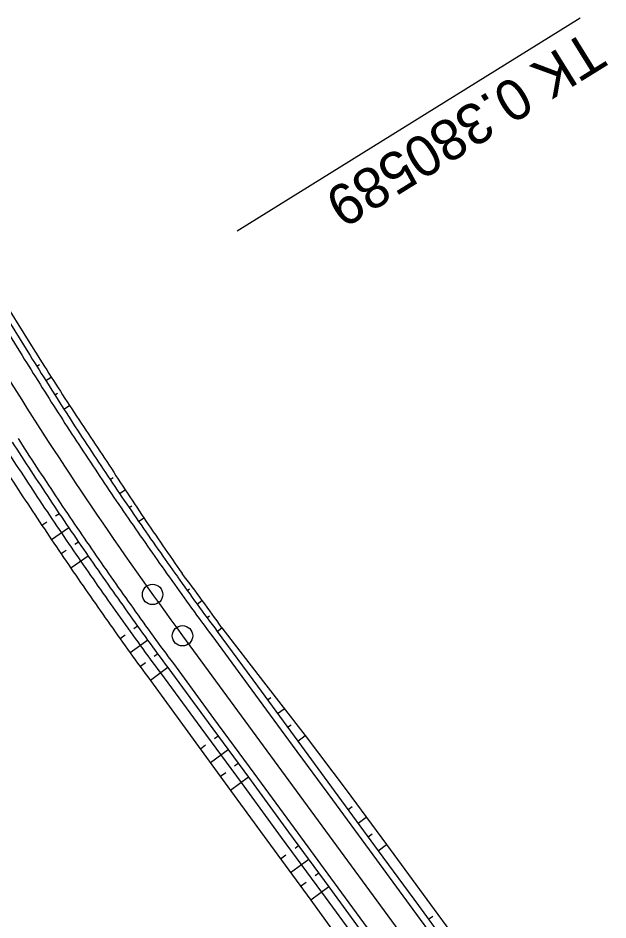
# Model space of a CAD drawing. Extents: x -481645 to -478728, y -1113199 to -1110710.
# Drawn here: x -480676.8 to -480633.4, y -1112872.3 to -1112806 of the extents above; entities that cross this region are included whole.
import ezdxf

# ---------------------------------------------------------------- set-up
doc = ezdxf.new("R2010")
doc.units = 0
for name, color, linetype in [('CP14_HATCH_SLOPE_R', 7, 'Continuous'), ('Vrstva 31', 7, 'Continuous'), ('Vrstva 32', 7, 'Continuous'), ('Vrstva 33', 7, 'Continuous'), ('Vrstva 34', 7, 'Continuous'), ('Vrstva 35', 7, 'Continuous'), ('Vrstva 37', 7, 'Continuous'), ('Vrstva 38', 7, 'Continuous'), ('Vrstva 39', 7, 'Continuous'), ('Vrstva 40', 7, 'Continuous')]:
    doc.layers.add(name, color=color, linetype=linetype)

msp = doc.modelspace()

# ---------------------------------------------------------------- linework, layer by layer
at = {"layer": 'CP14_HATCH_SLOPE_R'}
msp.add_line((-480664.724, -1112851.371), (-480634.276, -1112892.852), dxfattribs=at)
msp.add_arc((-480422.88, -1112673.855), 300, 211.85533, 216.27914, dxfattribs=at)
at = {"layer": 'Vrstva 31'}
for p, q in [((-480678.345, -1112826.011), (-480675.701, -1112830.255)), ((-480661.821, -1112850.789), (-480658.769, -1112854.751)), ((-480667.082, -1112854.65), (-480664.139, -1112858.692)), ((-480658.769, -1112854.751), (-480655.715, -1112858.711)), ((-480664.139, -1112858.692), (-480661.194, -1112862.733)), ((-480655.715, -1112858.711), (-480652.699, -1112862.7)), ((-480661.194, -1112862.733), (-480658.249, -1112866.774)), ((-480652.699, -1112862.7), (-480649.732, -1112866.725)), ((-480658.249, -1112866.774), (-480655.301, -1112870.813)), ((-480649.732, -1112866.725), (-480646.765, -1112870.749)), ((-480655.301, -1112870.813), (-480652.355, -1112874.852)), ((-480646.765, -1112870.749), (-480643.798, -1112874.774))]:
    msp.add_line(p, q, dxfattribs=at)
for centre, radius, start, end in [((-479922.472, -1112352.852), 891.778, 212.366886, 212.685556), ((-480424.277, -1112671.739), 297.238, 213.18635, 214.14131), ((-480423.024, -1112673.635), 303.787, 212.74733, 213.70226), ((-480420.584, -1112677.294), 297.252, 212.85556, 213.81059), ((-480422.254, -1112674.783), 303.794, 213.44157, 214.39651), ((-480421.236, -1112676.22), 297.31, 214.05258, 215.00756), ((-480422.209, -1112674.815), 303.813, 214.38669, 215.34163), ((-480783.207, -1112936.622), 148.667, 35.26462, 37.17881), ((-480545.358, -1112763.764), 151.912, 214.84324, 216.74722)]:
    msp.add_arc(centre, radius, start, end, dxfattribs=at)
at = {"layer": 'Vrstva 32'}
for p, q in [((-480666.336, -1112854.103), (-480663.378, -1112858.133)), ((-480663.378, -1112858.133), (-480660.419, -1112862.164)), ((-480660.419, -1112862.164), (-480657.46, -1112866.195)), ((-480657.46, -1112866.195), (-480654.502, -1112870.226)), ((-480654.502, -1112870.226), (-480651.543, -1112874.256))]:
    msp.add_line(p, q, dxfattribs=at)
for centre, radius, start, end in [((-480422.881, -1112673.855), 302.916, 212.69777, 213.6527), ((-480422.881, -1112673.855), 302.916, 213.6527, 214.60763), ((-480422.881, -1112673.855), 302.916, 214.60763, 215.56256), ((-480545.316, -1112763.033), 151.458, 215.05694, 216.96228)]:
    msp.add_arc(centre, radius, start, end, dxfattribs=at)
at = {"layer": 'Vrstva 33'}
for p, q in [((-480678.734, -1112826.253), (-480676.095, -1112830.5)), ((-480662.171, -1112851.046), (-480659.213, -1112855.076)), ((-480665.799, -1112853.708), (-480662.84, -1112857.739)), ((-480659.213, -1112855.076), (-480656.254, -1112859.107)), ((-480662.84, -1112857.739), (-480659.882, -1112861.77)), ((-480656.254, -1112859.107), (-480653.296, -1112863.138)), ((-480659.882, -1112861.77), (-480656.923, -1112865.801)), ((-480653.296, -1112863.138), (-480650.337, -1112867.169)), ((-480656.923, -1112865.801), (-480653.965, -1112869.831)), ((-480650.337, -1112867.169), (-480647.378, -1112871.199)), ((-480653.965, -1112869.831), (-480651.006, -1112873.862)), ((-480647.378, -1112871.199), (-480644.42, -1112875.23))]:
    msp.add_line(p, q, dxfattribs=at)
for centre, radius, start, end in [((-479919.133, -1112356.26), 893.25, 212.067306, 212.385897), ((-480422.881, -1112673.855), 297.75, 212.69777, 213.6527), ((-480422.881, -1112673.855), 302.25, 212.69777, 213.6527), ((-480422.881, -1112673.855), 297.75, 213.6527, 214.60763), ((-480422.881, -1112673.855), 302.25, 213.6527, 214.60763), ((-480422.881, -1112673.855), 297.75, 214.60763, 215.56256), ((-480422.881, -1112673.855), 302.25, 214.60763, 215.56256), ((-480543.224, -1112761.518), 148.875, 215.05399, 216.96753), ((-480545.046, -1112762.837), 151.125, 215.05656, 216.96295)]:
    msp.add_arc(centre, radius, start, end, dxfattribs=at)
at = {"layer": 'Vrstva 34'}
for p, q in [((-480679.159, -1112826.517), (-480676.52, -1112830.764)), ((-480662.574, -1112851.342), (-480659.616, -1112855.372)), ((-480665.396, -1112853.413), (-480662.437, -1112857.443)), ((-480659.616, -1112855.372), (-480656.657, -1112859.403)), ((-480662.437, -1112857.443), (-480659.479, -1112861.474)), ((-480656.657, -1112859.403), (-480653.699, -1112863.434)), ((-480659.479, -1112861.474), (-480656.52, -1112865.505)), ((-480653.699, -1112863.434), (-480650.74, -1112867.464)), ((-480656.52, -1112865.505), (-480653.562, -1112869.535)), ((-480650.74, -1112867.464), (-480647.781, -1112871.495)), ((-480653.562, -1112869.535), (-480650.603, -1112873.566)), ((-480647.781, -1112871.495), (-480644.823, -1112875.526))]:
    msp.add_line(p, q, dxfattribs=at)
for centre, radius, start, end in [((-479918.287, -1112355.726), 894.75, 212.067411, 212.385939), ((-480422.881, -1112673.855), 298.25, 212.69777, 213.6527), ((-480422.881, -1112673.855), 301.75, 212.69777, 213.6527), ((-480422.881, -1112673.855), 298.25, 213.6527, 214.60763), ((-480422.881, -1112673.855), 301.75, 213.6527, 214.60763), ((-480422.881, -1112673.855), 298.25, 214.60763, 215.56256), ((-480422.881, -1112673.855), 301.75, 214.60763, 215.56256), ((-480543.426, -1112761.664), 149.125, 215.05428, 216.96701), ((-480544.844, -1112762.691), 150.875, 215.05628, 216.96345)]:
    msp.add_arc(centre, radius, start, end, dxfattribs=at)
at = {"layer": 'Vrstva 35'}
for p, q in [((-480679.159, -1112826.517), (-480676.52, -1112830.764)), ((-480662.574, -1112851.342), (-480659.616, -1112855.372)), ((-480665.396, -1112853.413), (-480662.437, -1112857.443)), ((-480659.616, -1112855.372), (-480656.657, -1112859.403)), ((-480662.437, -1112857.443), (-480659.479, -1112861.474)), ((-480656.657, -1112859.403), (-480653.699, -1112863.434)), ((-480659.479, -1112861.474), (-480656.52, -1112865.505)), ((-480653.699, -1112863.434), (-480650.74, -1112867.464)), ((-480656.52, -1112865.505), (-480653.562, -1112869.535)), ((-480650.74, -1112867.464), (-480647.781, -1112871.495)), ((-480653.562, -1112869.535), (-480650.603, -1112873.566)), ((-480647.781, -1112871.495), (-480644.823, -1112875.526))]:
    msp.add_line(p, q, dxfattribs=at)
for centre, radius, start, end in [((-479918.287, -1112355.726), 894.75, 212.067411, 212.385939), ((-480422.881, -1112673.855), 298.25, 212.69777, 213.6527), ((-480422.881, -1112673.855), 301.75, 212.69777, 213.6527), ((-480422.881, -1112673.855), 298.25, 213.6527, 214.60763), ((-480422.881, -1112673.855), 301.75, 213.6527, 214.60763), ((-480422.881, -1112673.855), 298.25, 214.60763, 215.56256), ((-480422.881, -1112673.855), 301.75, 214.60763, 215.56256), ((-480543.426, -1112761.664), 149.125, 215.05428, 216.96701), ((-480544.844, -1112762.691), 150.875, 215.05628, 216.96345)]:
    msp.add_arc(centre, radius, start, end, dxfattribs=at)
at = {"layer": 'Vrstva 37'}
msp.add_line((-480635.481, -1112805.957), (-480660.708, -1112821.632), dxfattribs=at)
msp.add_circle((-480664.724, -1112851.371), 0.75, dxfattribs=at)
at = {"layer": 'Vrstva 38'}
msp.add_circle((-480666.925, -1112848.332), 0.75, dxfattribs=at)
at = {"layer": 'Vrstva 39'}
for p, q in [((-480675.438, -1112831.557), (-480675.238, -1112831.432)), ((-480675.038, -1112831.308), (-480675.038, -1112831.308)), ((-480674.778, -1112832.608), (-480674.374, -1112832.353)), ((-480674.115, -1112833.656), (-480673.911, -1112833.526)), ((-480673.706, -1112833.397), (-480673.706, -1112833.397)), ((-480673.447, -1112834.702), (-480673.034, -1112834.437)), ((-480670.041, -1112839.887), (-480669.827, -1112839.743)), ((-480669.613, -1112839.599), (-480669.613, -1112839.599)), ((-480669.348, -1112840.915), (-480668.935, -1112840.635)), ((-480668.649, -1112841.941), (-480668.45, -1112841.805)), ((-480668.252, -1112841.669), (-480668.252, -1112841.669)), ((-480667.947, -1112842.963), (-480667.565, -1112842.7)), ((-480664.371, -1112848.032), (-480664.2, -1112847.909)), ((-480664.03, -1112847.786), (-480664.03, -1112847.786)), ((-480663.643, -1112849.036), (-480663.299, -1112848.786)), ((-480662.911, -1112850.038), (-480662.738, -1112849.911)), ((-480662.565, -1112849.784), (-480662.565, -1112849.784)), ((-480662.171, -1112851.046), (-480661.821, -1112850.789)), ((-480658.473, -1112856.084), (-480658.24, -1112855.912)), ((-480658.006, -1112855.741), (-480658.006, -1112855.741)), ((-480657.733, -1112857.092), (-480657.242, -1112856.731)), ((-480656.479, -1112857.721), (-480656.479, -1112857.721)), ((-480656.994, -1112858.099), (-480656.736, -1112857.91)), ((-480656.254, -1112859.107), (-480655.715, -1112858.711)), ((-480652.556, -1112864.145), (-480652.257, -1112863.926)), ((-480651.958, -1112863.706), (-480651.958, -1112863.706)), ((-480651.816, -1112865.153), (-480651.216, -1112864.712)), ((-480651.077, -1112866.161), (-480650.776, -1112865.94)), ((-480650.474, -1112865.719), (-480650.474, -1112865.719)), ((-480650.337, -1112867.169), (-480649.732, -1112866.725)), ((-480646.639, -1112872.207), (-480646.331, -1112871.981)), ((-480646.023, -1112871.755), (-480646.023, -1112871.755))]:
    msp.add_line(p, q, dxfattribs=at)
at = {"layer": 'Vrstva 40'}
for p, q in [((-480673.777, -1112842.396), (-480674.054, -1112842.582)), ((-480674.692, -1112843.011), (-480675.055, -1112843.254)), ((-480673.072, -1112843.44), (-480674.351, -1112844.306)), ((-480673.278, -1112845.106), (-480673.642, -1112845.355)), ((-480672.364, -1112844.481), (-480672.639, -1112844.669)), ((-480671.651, -1112845.519), (-480672.929, -1112846.401)), ((-480668.021, -1112850.664), (-480668.291, -1112850.859)), ((-480668.93, -1112851.32), (-480669.3, -1112851.587)), ((-480667.282, -1112851.684), (-480668.561, -1112852.615)), ((-480666.539, -1112852.701), (-480666.808, -1112852.898)), ((-480667.447, -1112853.368), (-480667.818, -1112853.64)), ((-480665.799, -1112853.708), (-480667.082, -1112854.65)), ((-480662.101, -1112858.747), (-480662.37, -1112858.944)), ((-480663.02, -1112859.422), (-480663.403, -1112859.702)), ((-480661.361, -1112859.754), (-480662.666, -1112860.713)), ((-480660.621, -1112860.762), (-480660.89, -1112860.96)), ((-480661.544, -1112861.44), (-480661.93, -1112861.723)), ((-480659.882, -1112861.77), (-480661.194, -1112862.733)), ((-480656.184, -1112866.808), (-480656.452, -1112867.006)), ((-480657.117, -1112867.493), (-480657.512, -1112867.783)), ((-480655.444, -1112867.816), (-480656.775, -1112868.793)), ((-480654.704, -1112868.824), (-480654.973, -1112869.021)), ((-480655.64, -1112869.51), (-480656.038, -1112869.803)), ((-480653.965, -1112869.831), (-480655.301, -1112870.813))]:
    msp.add_line(p, q, dxfattribs=at)

# ---------------------------------------------------------------- texts
at = {"layer": 'Vrstva 37'}
msp.add_text('TK 0.380589', height=2.999, rotation=211.85534, dxfattribs=at).set_placement((-480634.953, -1112806.806))

doc.saveas('drawing.dxf')
